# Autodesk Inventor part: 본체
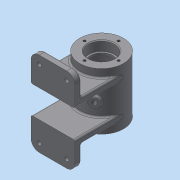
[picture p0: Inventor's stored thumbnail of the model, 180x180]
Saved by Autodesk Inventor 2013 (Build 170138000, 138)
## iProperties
Created: 2017-02
Part Number: 본체
Material: 일반
Document SubType Name: Modeling
Designer: dgall
Density: 1 g/cm^3
Mass: 131.396 g
Surface Area: 422.777 cm^2
Volume: 131.396 cm^3
Author: dgall
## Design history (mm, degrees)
sketch "스케치1"
  geometry: C1 r 27 at (0, 0); 1 further point
  constraints: 1 centre point, 1 coincident
  dimensions: "d0" = 54 diameter of C1
extrude "돌출1" new body sketch "스케치1" stored distance "d2" = 70; taper "d3" = 0 deg
sketch "스케치2"
  geometry: L1 (0, 45.412)-(0, -44.194); L2 (0, 35)-(16, 35); L3 (16, 35)-(16, 23.3); L4 (15.7, 23)-(14, 23); L5 (14, 23)-(14, 20); L6 (14, 20)-(19, 20); L7 (22, 17)-(22, -17); L8 (19, -20)-(14, -20); L9 (14, -20)-(14, -23); L10 (14, -23)-(15.7, -23); L11 (16, -23.3)-(16, -35); L12 (16, -35)-(0, -35); L13 (27, 35)-(-27, 35) reference; L14 (-27, -35)-(27, -35) reference; L15 (0, -35)-(0, 35); A1 r 0.3 centre (15.7, 23.3) between (15.7, 23) and (16, 23.3); A2 r 0.3 centre (15.7, -23.3) between (16, -23.3) and (15.7, -23); A3 r 3 centre (19, -17) between (19, -20) and (22, -17); A4 r 3 centre (19, 17) between (22, 17) and (19, 20); 1 further point
  constraints: 26 end point, 8 point on circle, 8 tangent, 7 parallel, 4 centre point, 4 equal length, 3 perpendicular, 3 point on line, 2 collinear, 2 equal radius, 2 midpoint, 1 vertical
  dimensions: "d4" = 28 diameter of L5 L1; "d6" = 32 diameter of L3 L1; "d7" = 44 diameter of L7 L1; "d8" = 12 distance between parallel lines of L4 L2; "d9" = 40 distance between parallel lines of L6 L8; "d10" = 0.3 radius of A1; "d11" = 3 radius of A3
revolve "회전1" sketch "스케치2" stored, may be unused: angle "d12" = 90 deg
node "작업 평면1"
sketch "스케치3"
  geometry: L1 (27, -17)-(-27, -17); L2 (-27, -17)-(-27, -52); L3 (-27, -52)-(27, -52); L4 (27, -52)-(27, -17); L5 (0, 0)-(0, -39.11)
  constraints: 10 end point, 3 parallel, 1 horizontal, 1 perpendicular, 1 other
  dimensions: "d14" = 17 distance from line of L1 L5.start; "d15" = 52 distance from line of L3 L5.start; "d16" = 54 distance between parallel lines of L2 L4
extrude "돌출2" join sketch "스케치3" distance "d17" = 8; taper "d18" = 0 deg
sketch "스케치4"
  geometry: L1 (-27, -17)-(27, -17) reference; L2 (-27, -52)-(-27, -17) reference; L3 (27, -17)-(27, -52) reference; L4 (-27, -25)-(27, -25); 1 further point
  constraints: 2 end point, 2 point on line, 1 perpendicular
  dimensions: "d19" = 8 distance between parallel lines of L4 L1
extrude "돌출3" join sketch "스케치4" stored distance "d20" = 8; taper "d21" = 0 deg
fillet "모깎기1" dims "d22" = 10
fillet "모깎기2" dims "d23" = 2
fillet "모깎기3" dims "d24" = 2
fillet "모깎기4" dims "d25" = 2
fillet "모깎기5" dims "d26" = 2
hole "구멍1" diameter "d29" = 5; stored, may be unused: countersink angle "d33" = 90 deg, drill point angle "d35" = 118 deg; dims "d27" = 10, "d28" = 10, "d30" = 6, "d31" = 9, "d32" = 3, "d34" = 8
sketch "스케치5"
  geometry: L1 (-12.5, 39.402)-(-17, 36.804); L2 (-17, 36.804)-(-21.5, 39.402); L3 (-21.5, 39.402)-(-21.5, 44.598); L4 (-21.5, 44.598)-(-17, 47.196); L5 (-17, 47.196)-(-12.5, 44.598); L6 (-12.5, 44.598)-(-12.5, 39.402); A1 r 8 centre (-17, 42) between (-17, 50) and (-25, 42) reference; 4 further points
  constraints: 12 end point, 1 coincident, 1 horizontal alignment, 1 midpoint, 1 vertical alignment, 14 other
extrude "돌출4" cut sketch "스케치5" distance "d36" = 3; taper "d37" = 0 deg
node "작업 평면3"
  node "작업 평면2"
sketch "스케치6"
  geometry: L1 (-27, -35)-(27, -35) reference; C1 r 5 at (0, -10); 1 further point
  constraints: 1 centre point, 1 vertical alignment
  dimensions: "d42" = 25 distance from line of C1.centre L1; "d43" = 10 diameter of C1
extrude "돌출5" join sketch "스케치6" stored distance "d44" = 3; taper "d45" = 0 deg
hole "구멍2" diameter "d48" = 5.188; stored, may be unused: countersink angle "d52" = 90 deg, drill point angle "d54" = 118 deg; dims "d46" = 10, "d47" = 10, "d49" = 10, "d50" = 9, "d51" = 3, "d53" = 8
sketch "스케치7"
  geometry: C1 r 16 at (0, 0) reference; 1 further point
  constraints: 1 vertical alignment
  dimensions: "d55" = 21 distance of point (0, 21) C1.centre
hole "구멍3" sketch "스케치7" at (0, 21) diameter "d56" = 3.242; stored, may be unused: countersink angle "d60" = 90 deg, drill point angle "d62" = 118 deg; dims "d57" = 8, "d58" = 9, "d59" = 3, "d61" = 10
sketch "스케치8"
  geometry: L1 (0, 0)-(16.339, -25.16); L2 (0, 0)-(0, -34.628)
  constraints: 4 end point, 2 point on line, 1 vertical
  dimensions: "d66" = 33 deg angle of L1 L2; "d67" = 30 distance of L1.end L1.start
node "작업 평면4"
sketch "스케치9"
  geometry: C1 r 6 at (0, 0); 1 further point
  constraints: 1 centre point, 1 coincident
  dimensions: "d68" = 12 diameter of C1
extrude "돌출6" join sketch "스케치9" stored distance "d70" = 3; taper "d71" = 0 deg
hole "구멍4" diameter "d74" = 5.188; stored, may be unused: countersink angle "d78" = 90 deg, drill point angle "d80" = 118 deg; dims "d72" = 10, "d73" = 10, "d75" = 8, "d76" = 9, "d77" = 3, "d79" = 10
node "작업 평면5"
sketch "스케치10"
  geometry: L1 (-27, -35)-(27, -35) reference; L2 (-27, -35)-(-27, 35) reference; 2 further points
  constraints: 1 other
  dimensions: "d81" = 35 distance from line of point (0, 0) L1; "d82" = 27 distance from line of point (0, 0) L2
feature "엠보싱1" sketch "스케치10" dims "d4" = 28, "d6" = 32, "d7" = 44, "d8" = 12, "d9" = 40, "d10" = 0.3, "d11" = 3, "d83" = 0.5, "d84" = 0
chamfer "모따기1" distance "d85" = 1; stored, may be unused: second distance "d86" = 2, angle "d87" = 45 deg
fillet "모깎기6" dims "d88" = 2
fillet "모깎기7" dims "d89" = 2
node "솔리드1"
pattern_linear "직사각형 패턴1" dims "d40" = 34
mirror "대칭1"
pattern_circular "원형 패턴1" dims angle "d64" = 360 deg
mirror "대칭2"
other parameters: "d41" = 5
